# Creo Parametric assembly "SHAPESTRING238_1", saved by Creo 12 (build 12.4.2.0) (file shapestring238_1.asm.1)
Units: Custom; MM, KILOGRAM, SECS

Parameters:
  PTC_WM_ITERATION = "0"
  PTC_WM_VERSION = "-.0"
  PTC_WM_LIFECYCLE_STATE = "In Work"
  PTC_WM_LIFECYCLE = "MO_CADDocument"
  PTC_WM_CREATED_BY = "Maximilian Roepper (Z0017RMS: MO)"
  PTC_WM_CREATED_ON = "18-Sep-26 11:36:42 AM"
  PTC_WM_MODIFIED_BY = "Maximilian Roepper (Z0017RMS: MO)"
  PTC_WM_MODIFIED_ON = "18-Sep-26 11:36:46 AM"
  PDMLINKNUMBER = "PDM000071454939"
  PTC_WM_NAME = "shapestring238_1.asm"
  PTC_WM_NUMBER = "PDM000071454939"

Other parameters: WEIGHT, WEIGHT_FACTOR, WEIGHT_ADD, MC_ERRORS, SUPPLIER, ISPOSITIONINGASSEMBLY

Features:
  1. coordinate system
  2. imported feature
  3. component "SHAPESTRING094_1"
  4. component "SHAPESTRING237_1"

Other named items: DRW_VIEW_ORG, ROUGH-GROB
